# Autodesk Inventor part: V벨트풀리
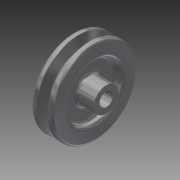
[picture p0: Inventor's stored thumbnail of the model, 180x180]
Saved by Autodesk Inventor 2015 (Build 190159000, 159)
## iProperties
Created: 2015-11
Part Number: V벨트풀리
Material: 강철, 탄소
Document SubType Name: Modeling
Designer: mduedu
Density: 1 g/cm^3
Appearance: 반광택
Author: mduedu
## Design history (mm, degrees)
sketch "스케치1"
  geometry: L1 (-9.5, 0)-(9.5, 0); L2 (0, 0)-(0, 37.7); L3 (-4.825, 37.7)-(-9.5, 37.7); L4 (-9.5, 37.7)-(-9.5, 0); L5 (0, 28.7)-(-2.074, 28.7); L6 (-2.074, 28.7)-(-4.825, 37.7); L7 (4.825, 37.7)-(9.5, 37.7); L8 (9.5, 37.7)-(9.5, 0); L9 (0, 28.7)-(2.074, 28.7); L10 (2.074, 28.7)-(4.825, 37.7); L11 (-9.5, 35)-(9.5, 35); 3 further points
  constraints: 22 end point, 7 point on line, 4 perpendicular, 3 symmetric about line, 1 coincident, 1 horizontal, 1 horizontal alignment, 1 midpoint, 1 vertical
  dimensions: "d0" = 19 distance of L1.start L1.end; "d2" = 75.4 diameter of L2.end L1 (derived); "d3" = 34 deg angle of L10 L6; "d4" = 6.3 distance between parallel lines of L11 L9; "d5" = 2.7 distance between parallel lines of L7 L11; "d6" = 8 distance of point (4, 35) point (-4, 35); "d7" = 70 diameter of L11 L1
revolve "회전1" sketch "스케치1" stored, may be unused: angle "d8" = 90 deg
sketch "스케치2"
  geometry: C1 r 24 at (0, 0); C2 r 11 at (0, 0); 1 further point
  constraints: 2 centre point, 2 coincident
  dimensions: "d9" = 48 diameter of C1; "d10" = 22 diameter of C2
extrude "돌출1" cut sketch "스케치2" distance "d11" = 6; taper "d12" = 0 deg
extrude "돌출3" join sketch "스케치2" distance "d37" = 10; taper "d38" = 0 deg
fillet "모깎기1" dims "d13" = 3
fillet "모깎기2" dims "d14" = 3
fillet "모깎기3" dims "d15" = 1, "d16" = 0.5, "d17" = 2
hole "구멍1" diameter "d20" = 12; stored, may be unused: countersink angle "d24" = 90 deg, drill point angle "d26" = 118 deg; dims "d21" = 6, "d22" = 4, "d23" = 2, "d25" = 8, "d39" = 10, "d40" = 10
sketch "스케치3"
  geometry: L1 (-2, 0)-(2, 0); L2 (2, 0)-(2, 7.8); L3 (2, 7.8)-(-2, 7.8); L4 (-2, 7.8)-(-2, 0); 2 further points
  constraints: 8 end point, 2 parallel, 1 coincident, 1 horizontal, 1 midpoint, 1 perpendicular
  dimensions: "d27" = 4 distance of L2.end L3.end; "d29" = 7.8 distance of L3.end L1.start
extrude "돌출2" cut sketch "스케치3" stored distance "d30" = 6; taper "d31" = 0 deg
chamfer "모따기1" distance "d32" = 0.5; stored, may be unused: second distance "d33" = 2, angle "d34" = 45 deg
node "작업 평면1"
sketch "스케치4"
  geometry: L1 (-19, 11)-(-19, -11) reference; 2 further points
  constraints: 1 horizontal alignment
  dimensions: "d41" = 25 distance from line of point (6, 0) L1
hole "구멍2" sketch "스케치4" at (6, 0) diameter "d42" = 2.459; stored, may be unused: countersink angle "d46" = 90 deg, drill point angle "d48" = 118 deg; dims "d43" = 6, "d44" = 4, "d45" = 2, "d47" = 8
node "작업 평면2"
node "솔리드1"
mirror "대칭1"
